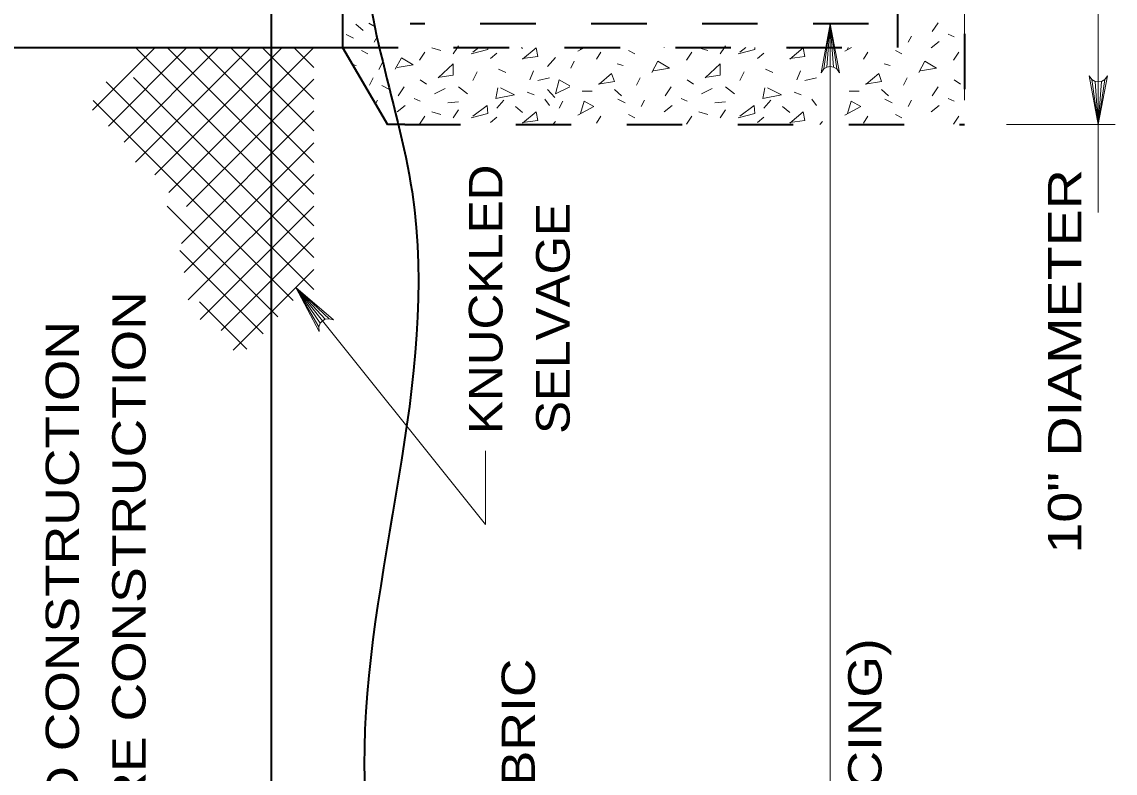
# Model space of a CAD drawing. Extents: x -46.1 to -39.3, y 101.7 to 111.8.
# Drawn here: x -43.658 to -41.688, y 107.135 to 108.489 of the extents above; entities that cross this region are included whole.
import ezdxf
from ezdxf.enums import TextEntityAlignment as Align

# ---------------------------------------------------------------- set-up
doc = ezdxf.new("R2010")
doc.units = 0
doc.header["$LTSCALE"] = 0.024
doc.linetypes.add('SHORT_DASHED', pattern=[2.7, 1.5, -1.2])
for name, color, linetype, lineweight in [('1', 7, 'Continuous', 35), ('10', 7, 'Continuous', 13), ('12', 7, 'Continuous', 53), ('6', 7, 'Continuous', 13)]:
    doc.layers.add(name, color=color, linetype=linetype, lineweight=lineweight)

msp = doc.modelspace()

# ---------------------------------------------------------------- linework, layer by layer
at = {"layer": '1'}
for p, q in [((-43.20892, 111.18012), (-43.20892, 105.48315)), ((-44.91852, 108.44275), (-43.08015, 108.44275)), ((-43.08015, 108.44275), (-42.99933, 108.30385)), ((-42.9679, 108.30385), (-42.99933, 108.30385))]:
    msp.add_line(p, q, dxfattribs=at)
at = {"layer": '1', "linetype": 'SHORT_DASHED'}
for p, q in [((-41.95892, 108.6675), (-41.95892, 108.30385)), ((-42.08015, 108.5286), (-42.08015, 108.44275)), ((-42.132, 108.48567), (-42.95835, 108.48567)), ((-43.08015, 108.44275), (-42.08015, 108.44275)), ((-42.9679, 108.30385), (-41.95892, 108.30385))]:
    msp.add_line(p, q, dxfattribs=at)
at = {"layer": '1'}
msp.add_lwpolyline([(-44.91852, 108.5286), (-43.08015, 108.5286), (-43.08015, 108.44275)], dxfattribs=at)
msp.add_spline([(-42.99933, 111.7931), (-43.04115, 111.45546), (-42.93785, 111.16262), (-43.02392, 110.54252), (-42.95506, 110.00852), (-43.02392, 109.56067), (-42.97227, 109.0439), (-43.04115, 108.68217), (-42.95506, 108.18263), (-43.04115, 107.1491), (-42.97227, 106.47729), (-43.04115, 105.66771), (-42.97227, 104.927), (-43.00671, 104.25521), (-43.00256, 103.82462)], degree=3, dxfattribs=at)
at = {"layer": '10'}
for p, q in [((-41.95892, 108.34769), (-41.95892, 108.96331)), ((-42.20108, 108.48567), (-42.20108, 105.33669)), ((-41.88317, 108.30385), (-41.68752, 108.30385))]:
    msp.add_line(p, q, dxfattribs=at)
for points in [[(-41.71781, 108.6675), (-41.71781, 108.30385), (-41.71781, 108.14565)], [(-42.20108, 108.48567), (-42.18454, 108.39742), (-42.18925, 108.40421), (-42.19517, 108.40771), (-42.20108, 108.40873), (-42.207, 108.40771), (-42.21292, 108.40421), (-42.21762, 108.39742), (-42.20108, 108.48567), (-42.21292, 108.40421), (-42.207, 108.40771), (-42.20108, 108.48567), (-42.20108, 108.40873), (-42.19517, 108.40771), (-42.20108, 108.48567), (-42.18925, 108.40421)], [(-41.71781, 108.30385), (-41.73438, 108.39212), (-41.72965, 108.38531), (-41.72373, 108.38181), (-41.71781, 108.38079), (-41.7119, 108.38181), (-41.70598, 108.38531), (-41.70127, 108.39212), (-41.71781, 108.30385), (-41.70598, 108.38531), (-41.7119, 108.38181), (-41.71781, 108.30385), (-41.71781, 108.38079), (-41.72373, 108.38181), (-41.71781, 108.30385), (-41.72965, 108.38531)], [(-42.82238, 107.71602), (-42.82238, 107.58281), (-43.16485, 108.01021)], [(-43.16485, 108.01021), (-43.09675, 107.95169), (-43.10467, 107.95404), (-43.11148, 107.95308), (-43.11673, 107.95017), (-43.12073, 107.94569), (-43.12315, 107.93925), (-43.12256, 107.93098), (-43.16485, 108.01021), (-43.12315, 107.93925), (-43.12073, 107.94569), (-43.16485, 108.01021), (-43.11673, 107.95017), (-43.11148, 107.95308), (-43.16485, 108.01021), (-43.10467, 107.95404)]]:
    msp.add_lwpolyline(points, dxfattribs=at)
at = {"layer": '6'}
for p, q in [((-43.05629, 108.48508), (-43.04346, 108.47385)), ((-43.033, 108.48671), (-43.02175, 108.48029)), ((-42.00629, 108.48752), (-42.01752, 108.47148)), ((-43.07365, 108.46625), (-43.06081, 108.45983)), ((-43.0236, 108.45223), (-43.01719, 108.46346)), ((-42.06085, 108.45223), (-42.05444, 108.46346)), ((-41.98865, 108.46667), (-41.97742, 108.46185)), ((-43.418, 108.44275), (-43.53108, 108.32965)), ((-43.36085, 108.44275), (-43.50252, 108.30108)), ((-43.30373, 108.44275), (-43.47396, 108.2725)), ((-43.45383, 108.44275), (-43.13229, 108.12121)), ((-43.24658, 108.44275), (-43.45335, 108.23598)), ((-43.18944, 108.44275), (-43.41883, 108.21335)), ((-43.39669, 108.44275), (-43.13229, 108.17835)), ((-43.13229, 108.44275), (-43.39325, 108.18179)), ((-43.33954, 108.44275), (-43.13229, 108.2355)), ((-43.28242, 108.44275), (-43.13229, 108.29263)), ((-43.22527, 108.44275), (-43.13229, 108.34977)), ((-43.16812, 108.44275), (-43.13229, 108.40692)), ((-42.98169, 108.44275), (-42.98187, 108.44258)), ((-42.91931, 108.44258), (-42.90325, 108.43777)), ((-42.88079, 108.43135), (-42.87321, 108.44275)), ((-42.87321, 108.44275), (-42.87117, 108.44581)), ((-42.8346, 108.44275), (-42.8455, 108.43456)), ((-42.75765, 108.44275), (-42.75565, 108.44098)), ((-42.65615, 108.43617), (-42.64433, 108.44275)), ((-42.65037, 108.44275), (-42.65133, 108.43937)), ((-42.50031, 108.44275), (-42.5005, 108.44258)), ((-42.43794, 108.44258), (-42.42188, 108.43777)), ((-42.39942, 108.43135), (-42.39183, 108.44275)), ((-42.39183, 108.44275), (-42.38979, 108.44581)), ((-42.35323, 108.44275), (-42.36413, 108.43456)), ((-42.27627, 108.44275), (-42.27425, 108.44098)), ((-42.17477, 108.43617), (-42.16296, 108.44275)), ((-42.169, 108.44275), (-42.16996, 108.43937)), ((-42.00469, 108.45383), (-42.01912, 108.44258)), ((-43.04606, 108.43777), (-43.03483, 108.43135)), ((-42.93215, 108.43456), (-42.94177, 108.42012)), ((-42.8134, 108.42333), (-42.80217, 108.43296)), ((-42.69627, 108.42494), (-42.71071, 108.4089)), ((-42.62246, 108.42173), (-42.61444, 108.43456)), ((-42.56469, 108.43777), (-42.55346, 108.43135)), ((-42.45077, 108.43456), (-42.4604, 108.42012)), ((-42.33202, 108.42333), (-42.32079, 108.43296)), ((-42.14108, 108.42173), (-42.13306, 108.43456)), ((-42.08331, 108.43777), (-42.07208, 108.43135)), ((-41.9694, 108.43456), (-41.97902, 108.42012)), ((-43.06252, 108.41246), (-43.05569, 108.4105)), ((-43.0085, 108.41615), (-43.01492, 108.40331)), ((-42.79896, 108.40408), (-42.78612, 108.39767)), ((-42.66256, 108.41852), (-42.66898, 108.40569)), ((-42.58554, 108.41371), (-42.57431, 108.4105)), ((-42.31758, 108.40408), (-42.30475, 108.39767)), ((-42.10417, 108.41371), (-42.09294, 108.4105)), ((-43.45702, 108.38879), (-43.13229, 108.06408)), ((-43.13229, 108.3856), (-43.36171, 108.15621)), ((-43.03162, 108.37521), (-43.02521, 108.38804)), ((-42.94017, 108.38483), (-42.92894, 108.37681)), ((-42.8455, 108.38323), (-42.83748, 108.39927)), ((-42.73637, 108.40087), (-42.74279, 108.38483)), ((-42.7075, 108.38804), (-42.72835, 108.38323)), ((-42.55025, 108.37521), (-42.54383, 108.38804)), ((-42.45879, 108.38483), (-42.44756, 108.37681)), ((-42.36413, 108.38323), (-42.3561, 108.39927)), ((-42.255, 108.40087), (-42.26142, 108.38483)), ((-42.22612, 108.38804), (-42.24698, 108.38323)), ((-42.06887, 108.37521), (-42.06246, 108.38804)), ((-41.97742, 108.38483), (-41.96619, 108.37681)), ((-43.50644, 108.38108), (-43.13229, 108.00694)), ((-43.00952, 108.3745), (-42.99669, 108.36808)), ((-42.96904, 108.372), (-42.98027, 108.35594)), ((-42.89523, 108.36879), (-42.9145, 108.35915)), ((-42.87117, 108.372), (-42.85513, 108.35915)), ((-42.71071, 108.36719), (-42.69787, 108.35273)), ((-42.64813, 108.36398), (-42.63048, 108.36398)), ((-42.59035, 108.36719), (-42.57752, 108.35594)), ((-42.48767, 108.372), (-42.4989, 108.35594)), ((-42.41385, 108.36879), (-42.4331, 108.35915)), ((-42.38979, 108.372), (-42.37375, 108.35915)), ((-42.16675, 108.36398), (-42.1491, 108.36398)), ((-42.10898, 108.36719), (-42.09615, 108.35594)), ((-42.00629, 108.372), (-42.01752, 108.35594)), ((-43.53004, 108.34754), (-43.1694, 107.9869)), ((-43.02104, 108.34117), (-43.01719, 108.34792)), ((-42.9514, 108.35112), (-42.94017, 108.34631)), ((-42.89042, 108.3431), (-42.87117, 108.34471)), ((-42.80217, 108.33348), (-42.78933, 108.34792)), ((-42.7476, 108.36235), (-42.73477, 108.35754)), ((-42.71552, 108.34952), (-42.7075, 108.33829)), ((-42.68344, 108.34631), (-42.68985, 108.33348)), ((-42.58394, 108.34952), (-42.5711, 108.3431)), ((-42.54223, 108.33669), (-42.53581, 108.34792)), ((-42.47002, 108.35112), (-42.45879, 108.34631)), ((-42.40904, 108.3431), (-42.38979, 108.34471)), ((-42.32079, 108.33348), (-42.30796, 108.34792)), ((-42.26623, 108.36235), (-42.2534, 108.35754)), ((-42.23415, 108.34952), (-42.22612, 108.33829)), ((-42.10256, 108.34952), (-42.08973, 108.3431)), ((-42.06085, 108.33669), (-42.05444, 108.34792)), ((-41.98865, 108.35112), (-41.97742, 108.34631)), ((-43.13229, 108.32846), (-43.3709, 108.08987)), ((-42.96744, 108.33829), (-42.98187, 108.32706)), ((-42.91931, 108.32706), (-42.90325, 108.32225)), ((-42.88079, 108.31583), (-42.87117, 108.33027)), ((-42.76848, 108.33669), (-42.75565, 108.32546)), ((-42.48606, 108.33829), (-42.5005, 108.32706)), ((-42.43794, 108.32706), (-42.42188, 108.32225)), ((-42.39942, 108.31583), (-42.38979, 108.33027)), ((-42.2871, 108.33669), (-42.27425, 108.32546)), ((-42.00469, 108.33829), (-42.01912, 108.32706)), ((-42.93215, 108.31904), (-42.94177, 108.3046)), ((-42.8134, 108.30781), (-42.80217, 108.31744)), ((-42.69627, 108.30942), (-42.70127, 108.30385)), ((-42.62246, 108.30621), (-42.61444, 108.31904)), ((-42.56469, 108.32225), (-42.55346, 108.31583)), ((-42.45077, 108.31904), (-42.4604, 108.3046)), ((-42.33202, 108.30781), (-42.32079, 108.31744)), ((-42.2149, 108.30942), (-42.2199, 108.30385)), ((-42.14108, 108.30621), (-42.13306, 108.31904)), ((-42.08331, 108.32225), (-42.07208, 108.31583)), ((-41.9694, 108.31904), (-41.97902, 108.3046)), ((-43.13229, 108.27131), (-43.36617, 108.03744)), ((-43.13229, 108.21419), (-43.35848, 107.988)), ((-43.39667, 108.15702), (-43.19698, 107.95733)), ((-43.13229, 108.15704), (-43.33687, 107.95248)), ((-43.13229, 108.0999), (-43.29937, 107.93283)), ((-43.37356, 108.07677), (-43.22354, 107.92677)), ((-43.13229, 108.04277), (-43.27775, 107.89731)), ((-43.33854, 107.98462), (-43.2531, 107.89917))]:
    msp.add_line(p, q, dxfattribs=at)
for points in [[(-42.84871, 108.43135), (-42.81821, 108.43937), (-42.81858, 108.44275)], [(-42.75565, 108.42333), (-42.72835, 108.42654), (-42.73156, 108.44258), (-42.75565, 108.42173)], [(-42.36733, 108.43135), (-42.33683, 108.43937), (-42.33721, 108.44275)], [(-42.27425, 108.42333), (-42.24698, 108.42654), (-42.25019, 108.44258), (-42.27425, 108.42173)], [(-42.98533, 108.4036), (-42.9741, 108.42448), (-42.95323, 108.41163), (-42.98212, 108.40681)], [(-42.90485, 108.38965), (-42.88079, 108.39285), (-42.88079, 108.41371), (-42.90806, 108.38804)], [(-42.52298, 108.39767), (-42.51173, 108.41852), (-42.49087, 108.40569), (-42.51977, 108.40087)], [(-42.42348, 108.38965), (-42.39942, 108.39285), (-42.39942, 108.41371), (-42.42669, 108.38804)], [(-42.0416, 108.39767), (-42.03035, 108.41852), (-42.0095, 108.40569), (-42.0384, 108.40087)], [(-42.67058, 108.372), (-42.69627, 108.35915), (-42.68985, 108.38483), (-42.67058, 108.3736)], [(-42.61925, 108.37681), (-42.59035, 108.38162), (-42.59519, 108.39606), (-42.61765, 108.37681)], [(-42.13788, 108.37681), (-42.10898, 108.38162), (-42.11379, 108.39606), (-42.13627, 108.37681)], [(-42.80056, 108.3704), (-42.80377, 108.35112), (-42.77008, 108.35754), (-42.79575, 108.3704)], [(-42.31919, 108.3704), (-42.3224, 108.35112), (-42.28871, 108.35754), (-42.31437, 108.3704)], [(-42.65615, 108.32065), (-42.62727, 108.33669), (-42.64492, 108.34631), (-42.65133, 108.32385)], [(-42.17477, 108.32065), (-42.1459, 108.33669), (-42.16354, 108.34631), (-42.16996, 108.32385)], [(-42.84871, 108.31583), (-42.81821, 108.32385), (-42.81981, 108.33829), (-42.8455, 108.31904)], [(-42.75565, 108.30781), (-42.72835, 108.31102), (-42.73156, 108.32706), (-42.75565, 108.30621)], [(-42.36733, 108.31583), (-42.33683, 108.32385), (-42.33844, 108.33829), (-42.36413, 108.31904)], [(-42.27425, 108.30781), (-42.24698, 108.31102), (-42.25019, 108.32706), (-42.27425, 108.30621)]]:
    msp.add_lwpolyline(points, dxfattribs=at)

# ---------------------------------------------------------------- texts
at = {"layer": '12'}
for s, height, width, p in [('KNUCKLED', 0.06061, 1.1, (-42.79206, 107.74631)), ('SELVAGE', 0.06061, 1.1, (-42.67084, 107.74631)), ('MD 690.12 SQUARE CONSTRUCTION', 0.06, 1.2, (-43.43555, 106.29677)), ('MD 690.11 ROUND CONSTRUCTION', 0.06, 1.2, (-43.55555, 106.29677)), ('SPACE UNDER FABRIC', 0.06, 1.2, (-42.73355, 106.26592))]:
    msp.add_text(s, height=height, rotation=90, dxfattribs=dict(at, width=width)).set_placement(p)
at = {"layer": '12', "width": 1.25}
msp.add_text('10" DIAMETER', height=0.06, rotation=90, dxfattribs=at).set_placement((-41.74849, 108.2237), align=Align.RIGHT)
at = {"layer": '12', "width": 1.2}
msp.add_text('(MAXIMUM SPACING)', height=0.06, rotation=90, dxfattribs=at).set_placement((-42.10875, 106.8831), align=Align.CENTER)

doc.saveas('drawing.dxf')
